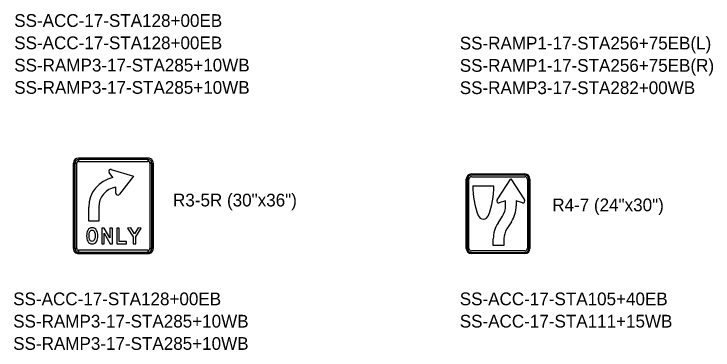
# Model space of a CAD drawing. Extents: x 620856.8 to 620948.6, y 415598.8 to 415658.2.
# Drawn here: x 620900.16 to 620922.1, y 415616.01 to 415626.56 of the extents above; entities that cross this region are included whole.
import ezdxf

# ---------------------------------------------------------------- set-up
doc = ezdxf.new("R2010")
doc.units = 0
doc.layers.add('SIGNS', color=7, linetype='Continuous')

msp = doc.modelspace()

# ---------------------------------------------------------------- linework, layer by layer
at = {"layer": 'SIGNS'}
for p, q in [((620904.369, 415622.041), (620902.181, 415622.041)), ((620902.181, 415622.041), (620904.369, 415622.041)), ((620902.181, 415621.936), (620902.181, 415621.999)), ((620904.369, 415621.999), (620904.369, 415621.936)), ((620902.025, 415621.884), (620902.025, 415619.197)), ((620902.025, 415619.197), (620902.025, 415621.884)), ((620902.067, 415621.884), (620902.129, 415621.884)), ((620903.213, 415621.686), (620903.911, 415621.478)), ((620904.421, 415621.884), (620904.484, 415621.884)), ((620904.525, 415619.197), (620904.525, 415621.884)), ((620904.525, 415621.884), (620904.525, 415619.197)), ((620903.259, 415621.427), (620903.145, 415621.59)), ((620903.911, 415621.478), (620903.465, 415620.903)), ((620914.353, 415619.207), (620914.353, 415621.374)), ((620916.353, 415621.374), (620916.353, 415619.207)), ((620903.353, 415620.941), (620903.352, 415621.126)), ((620914.555, 415621.169), (620915.222, 415621.169)), ((620902.504, 415620.062), (620902.504, 415620.499)), ((620902.817, 415620.499), (620902.817, 415620.062)), ((620915.349, 415620.001), (620915.492, 415620.222)), ((620902.817, 415620.062), (620902.504, 415620.062)), ((620915.772, 415620.04), (620915.629, 415619.82)), ((620902.129, 415619.197), (620902.067, 415619.197)), ((620902.181, 415619.082), (620902.181, 415619.145)), ((620902.181, 415619.041), (620904.369, 415619.041)), ((620904.369, 415619.041), (620902.181, 415619.041)), ((620904.369, 415619.145), (620904.369, 415619.082)), ((620904.484, 415619.197), (620904.421, 415619.197)), ((620916.186, 415619.041), (620914.52, 415619.041))]:
    msp.add_line(p, q, dxfattribs=at)
for points in [[(620904.369, 415621.999), (620902.181, 415621.999), (620902.181, 415621.936), (620904.369, 415621.936), (620904.369, 415621.999), (620904.369, 415621.999)], [(620902.067, 415621.884), (620902.067, 415619.197), (620902.129, 415619.197), (620902.129, 415621.884), (620902.067, 415621.884), (620902.067, 415621.884)], [(620904.484, 415619.197), (620904.484, 415621.884), (620904.421, 415621.884), (620904.421, 415619.197), (620904.484, 415619.197), (620904.484, 415619.197)], [(620902.912, 415619.353), (620902.989, 415619.353), (620902.989, 415619.688), (620903.178, 415619.353), (620903.248, 415619.353), (620903.248, 415619.844), (620903.162, 415619.844), (620903.162, 415619.532), (620902.989, 415619.844), (620902.912, 415619.844)], [(620903.383, 415619.353), (620903.689, 415619.353), (620903.689, 415619.425), (620903.459, 415619.425), (620903.459, 415619.844), (620903.383, 415619.844)], [(620903.725, 415619.844), (620903.9, 415619.567), (620903.9, 415619.353), (620903.978, 415619.353), (620903.978, 415619.567), (620904.151, 415619.844), (620904.058, 415619.848), (620903.938, 415619.658), (620903.82, 415619.848)], [(620902.181, 415619.082), (620904.369, 415619.082), (620904.369, 415619.145), (620902.181, 415619.145), (620902.181, 415619.082), (620902.181, 415619.082)]]:
    msp.add_lwpolyline(points, close=True, dxfattribs=at)
for points in [[(620914.52, 415621.541), (620915.353, 415621.541), (620916.186, 415621.541)], [(620916.186, 415621.507), (620914.52, 415621.507)], [(620914.52, 415621.457), (620916.186, 415621.457)], [(620914.386, 415621.374), (620914.386, 415619.207)], [(620914.436, 415619.207), (620914.436, 415621.374)], [(620915.323, 415620.729), (620915.753, 415621.387), (620916.183, 415620.729)], [(620916.27, 415621.374), (620916.27, 415619.207)], [(620916.32, 415619.207), (620916.32, 415621.374)], [(620915.586, 415620.54), (620915.586, 415620.696), (620915.39, 415620.636)], [(620916.116, 415620.636), (620915.92, 415620.696), (620915.92, 415620.54)], [(620902.788, 415619.599), (620902.785, 415619.65), (620902.779, 415619.696), (620902.768, 415619.736), (620902.752, 415619.771), (620902.726, 415619.807), (620902.694, 415619.833), (620902.655, 415619.848), (620902.609, 415619.853), (620902.565, 415619.848), (620902.528, 415619.832), (620902.496, 415619.806), (620902.471, 415619.769), (620902.456, 415619.734), (620902.445, 415619.695), (620902.439, 415619.65), (620902.437, 415619.602), (620902.439, 415619.551), (620902.445, 415619.506), (620902.456, 415619.466), (620902.471, 415619.43), (620902.497, 415619.392), (620902.529, 415619.365), (620902.568, 415619.349), (620902.613, 415619.344), (620902.657, 415619.349), (620902.695, 415619.365), (620902.727, 415619.392), (620902.753, 415619.429), (620902.768, 415619.465), (620902.779, 415619.505), (620902.785, 415619.55), (620902.788, 415619.599)], [(620902.706, 415619.604), (620902.701, 415619.541), (620902.689, 415619.49), (620902.674, 415619.461), (620902.656, 415619.44), (620902.633, 415619.428), (620902.607, 415619.424), (620902.582, 415619.428), (620902.561, 415619.44), (620902.543, 415619.461), (620902.53, 415619.49), (620902.518, 415619.54), (620902.514, 415619.6), (620902.518, 415619.66), (620902.53, 415619.711), (620902.543, 415619.74), (620902.56, 415619.761), (620902.581, 415619.774), (620902.605, 415619.778), (620902.632, 415619.774), (620902.654, 415619.763), (620902.673, 415619.743), (620902.688, 415619.717), (620902.701, 415619.667), (620902.706, 415619.604)], [(620915.534, 415619.502), (620915.534, 415619.294), (620915.201, 415619.294), (620915.201, 415619.502)], [(620916.186, 415619.124), (620914.52, 415619.124)], [(620914.52, 415619.074), (620916.186, 415619.074)]]:
    msp.add_lwpolyline(points, dxfattribs=at)
for centre, radius, start, end in [((620902.181, 415621.884), 0.156, 90.0002, 179.9998), ((620902.181, 415621.884), 0.156, 90.0002, 179.9998), ((620902.181, 415621.884), 0.115, 90.0002, 179.9998), ((620902.181, 415621.884), 0.0521, 90.0002, 179.9998), ((620904.369, 415621.884), 0.156, 360, 90.0002), ((620904.369, 415621.884), 0.156, 360, 90.0002), ((620904.369, 415621.884), 0.115, 360, 90.0002), ((620904.369, 415621.884), 0.0521, 360, 90.0002), ((620903.196, 415621.626), 0.0625, 73.4349, 215.2064), ((620914.52, 415621.374), 0.167, 90, 180), ((620914.52, 415621.374), 0.133, 90, 180), ((620914.52, 415621.374), 0.0833, 90, 180), ((620916.186, 415621.374), 0.167, 0, 90), ((620916.186, 415621.374), 0.133, 0, 90), ((620916.186, 415621.374), 0.0833, 0, 90), ((620903.452, 415620.499), 0.948, 101.7493, 179.9998), ((620903.452, 415620.499), 0.635, 99.0959, 179.9998), ((620917.055, 415621.16), 2.5, 179.8139, 201.5556), ((620912.722, 415621.16), 2.5, 338.4444, 0.1861), ((620903.416, 415620.941), 0.0625, 180.4743, 322.2458), ((620915.003, 415620.54), 0.583, 326.9794, 0), ((620915.003, 415620.54), 0.917, 326.9794, 360), ((620914.889, 415620.294), 0.167, 198.0438, 341.9562), ((620916.118, 415619.502), 0.917, 146.9794, 180), ((620916.118, 415619.502), 0.583, 146.9827, 180), ((620902.181, 415619.197), 0.156, 179.9998, 270.0001), ((620902.181, 415619.197), 0.156, 179.9998, 270.0001), ((620902.181, 415619.197), 0.115, 179.9998, 270.0001), ((620902.181, 415619.197), 0.0521, 179.9998, 270.0001), ((620904.369, 415619.197), 0.156, 270.0001, 0.0003), ((620904.369, 415619.197), 0.115, 270.0001, 0.0003), ((620904.369, 415619.197), 0.0521, 270.0001, 0.0003), ((620904.369, 415619.197), 0.156, 270.0001, 0.0003), ((620914.52, 415619.207), 0.167, 180, 270), ((620914.52, 415619.207), 0.133, 180, 270), ((620914.52, 415619.207), 0.0833, 180, 270), ((620916.186, 415619.207), 0.167, 270, 0), ((620916.186, 415619.207), 0.133, 270, 0), ((620916.186, 415619.207), 0.0833, 270, 0)]:
    msp.add_arc(centre, radius, start, end, dxfattribs=at)
for centre, major_axis, start_param, end_param in [((620915.373, 415620.695), (0, 0.0617), 0.977608, 3.428881), ((620916.133, 415620.695), (0, -0.0617), 5.995897, 8.44717)]:
    msp.add_ellipse(centre, major_axis=major_axis, ratio=0.968523, start_param=start_param, end_param=end_param, dxfattribs=at)

# ---------------------------------------------------------------- texts
for s, p in [('SS-ACC-17-STA128+00EB', (620900.166, 415626.159)), ('SS-ACC-17-STA128+00EB', (620900.166, 415625.459)), ('SS-RAMP1-17-STA256+75EB(L)', (620914.149, 415625.45)), ('SS-RAMP3-17-STA285+10WB', (620900.166, 415624.759)), ('SS-RAMP1-17-STA256+75EB(R)', (620914.149, 415624.75)), ('SS-RAMP3-17-STA285+10WB', (620900.166, 415624.059)), ('SS-RAMP3-17-STA282+00WB', (620914.149, 415624.05)), ('R3-5R (30"x36")', (620905.149, 415620.523)), ('R4-7 (24"x30")', (620917.052, 415620.371)), ('SS-ACC-17-STA128+00EB', (620900.133, 415617.42)), ('SS-ACC-17-STA105+40EB', (620914.149, 415617.42)), ('SS-RAMP3-17-STA285+10WB', (620900.133, 415616.72)), ('SS-ACC-17-STA111+15WB', (620914.149, 415616.72)), ('SS-RAMP3-17-STA285+10WB', (620900.133, 415616.02))]:
    msp.add_text(s, height=0.4, rotation=0, dxfattribs=at).set_placement(p)

doc.saveas('drawing.dxf')
